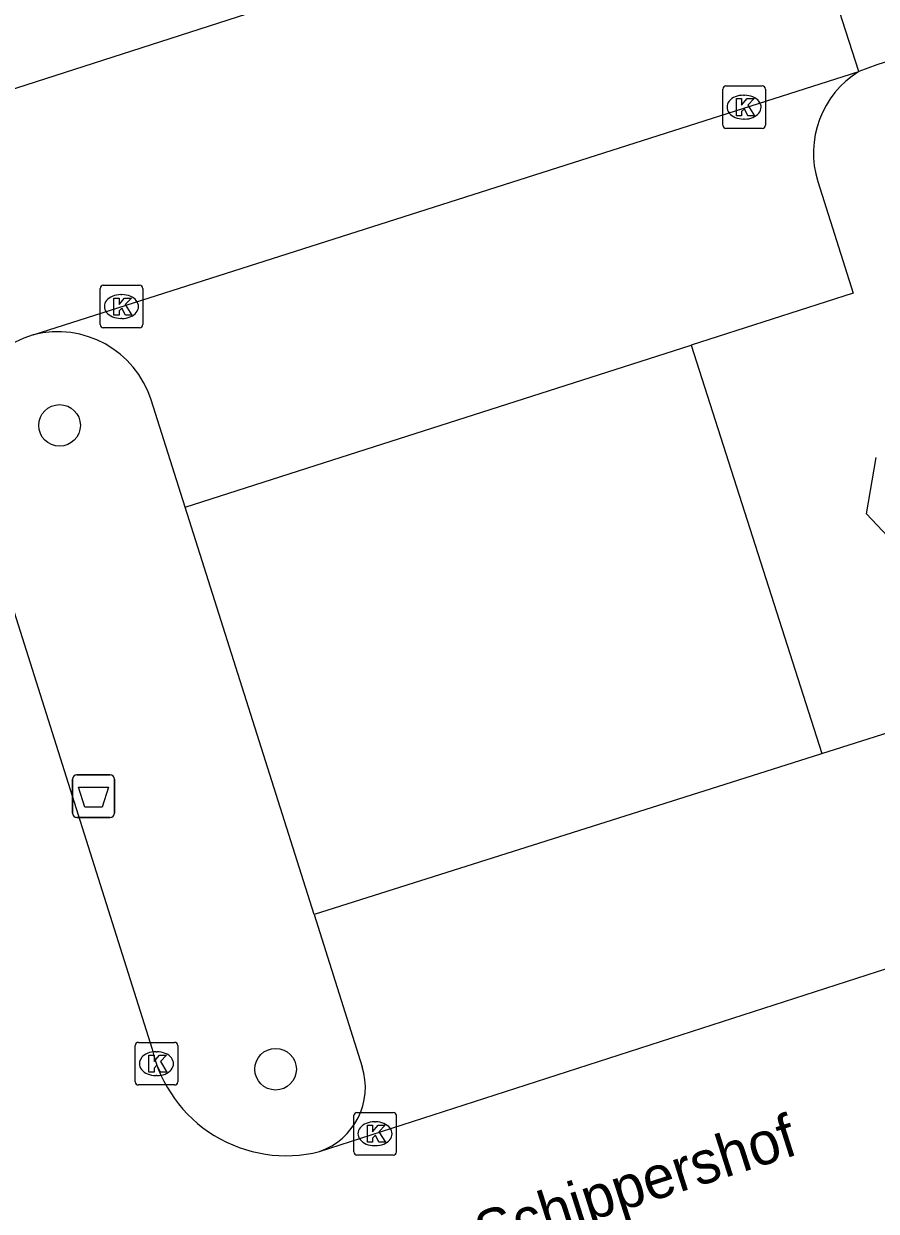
# Model space of a CAD drawing. Extents: x 159377 to 159983, y 382996 to 383595.
# Drawn here: x 159523.61 to 159543.65, y 383099.82 to 383127.71 of the extents above; entities that cross this region are included whole.
import ezdxf

# ---------------------------------------------------------------- set-up
doc = ezdxf.new("R2010")
doc.units = 0
for name, color, linetype in [('IMGEO_Afvalbak', 7, 'Continuous'), ('IMGEO_Boom', 7, 'Continuous'), ('IMGEO_Groenvoorziening', 7, 'Continuous'), ('IMGEO_Kolk', 7, 'Continuous'), ('IMGEO_Openbare_ruimte_label', 7, 'Continuous'), ('IMGEO_Parkeervlak_open', 7, 'Continuous'), ('IMGEO_Rijbaan_lokaal_open', 7, 'Continuous')]:
    doc.layers.add(name, color=color, linetype=linetype)

msp = doc.modelspace()

# ---------------------------------------------------------------- linework, layer by layer
at = {"layer": 'IMGEO_Afvalbak'}
for p, q in [((159524.758, 383109.167), (159524.758, 383109.967)), ((159524.758, 383109.967), (159524.758, 383109.167)), ((159524.858, 383110.067), (159525.648, 383110.067)), ((159525.648, 383110.067), (159524.858, 383110.067)), ((159525.748, 383109.967), (159525.748, 383109.167)), ((159525.748, 383109.167), (159525.748, 383109.967)), ((159525.648, 383109.067), (159524.858, 383109.067)), ((159524.858, 383109.067), (159525.648, 383109.067))]:
    msp.add_line(p, q, dxfattribs=at)
msp.add_lwpolyline([(159524.901, 383109.781), (159525.605, 383109.781), (159525.456, 383109.311), (159525.05, 383109.311), (159524.901, 383109.781)], dxfattribs=at)
for centre, start, end in [((159524.858, 383109.967), 90, 180), ((159524.858, 383109.967), 90, 180), ((159525.648, 383109.967), 0, 90), ((159525.648, 383109.967), 360, 90), ((159524.858, 383109.167), 180, 270), ((159524.858, 383109.167), 180, 270), ((159525.648, 383109.167), 270, 0), ((159525.648, 383109.167), 270, 0)]:
    msp.add_arc(centre, 0.1, start, end, dxfattribs=at)
at = {"layer": 'IMGEO_Boom'}
for centre in [(159524.456, 383118.278), (159529.533, 383103.152)]:
    msp.add_circle(centre, 0.489, dxfattribs=at)
at = {"layer": 'IMGEO_Groenvoorziening'}
for points in [[(159539.299, 383120.164), (159542.373, 383110.568)], [(159544.43, 383115.124), (159543.419, 383116.198), (159543.65, 383117.526)], [(159530.436, 383106.788), (159527.406, 383116.357)]]:
    msp.add_lwpolyline(points, dxfattribs=at)
at = {"layer": 'IMGEO_Kolk'}
for p, q in [((159540.042, 383125.329), (159540.042, 383126.181)), ((159540.117, 383126.255), (159540.969, 383126.255)), ((159541.043, 383126.181), (159541.043, 383125.329)), ((159540.53, 383126.035), (159540.555, 383126.035)), ((159540.553, 383125.475), (159540.528, 383125.475)), ((159540.969, 383125.255), (159540.117, 383125.255)), ((159525.409, 383120.645), (159525.409, 383121.497)), ((159525.484, 383121.571), (159526.336, 383121.571)), ((159526.41, 383121.497), (159526.41, 383120.645)), ((159525.897, 383121.351), (159525.922, 383121.351)), ((159526.336, 383120.571), (159525.484, 383120.571)), ((159525.92, 383120.791), (159525.895, 383120.791)), ((159526.307, 383103.783), (159527.159, 383103.783)), ((159526.232, 383102.857), (159526.232, 383103.709)), ((159526.72, 383103.563), (159526.745, 383103.563)), ((159527.233, 383103.709), (159527.233, 383102.857)), ((159526.743, 383103.003), (159526.718, 383103.003)), ((159527.159, 383102.783), (159526.307, 383102.783)), ((159531.444, 383102.136), (159532.296, 383102.136)), ((159531.369, 383101.21), (159531.369, 383102.062)), ((159531.857, 383101.916), (159531.882, 383101.916)), ((159532.37, 383102.062), (159532.37, 383101.21)), ((159531.88, 383101.356), (159531.855, 383101.356)), ((159532.296, 383101.136), (159531.444, 383101.136))]:
    msp.add_line(p, q, dxfattribs=at)
for points in [[(159540.042, 383125.329), (159540.042, 383126.181)], [(159540.117, 383126.255), (159540.969, 383126.255)], [(159541.043, 383126.181), (159541.043, 383125.329)], [(159540.363, 383125.955), (159540.486, 383125.955), (159540.486, 383125.804), (159540.616, 383125.955), (159540.78, 383125.955), (159540.634, 383125.804), (159540.787, 383125.555), (159540.635, 383125.555), (159540.55, 383125.719), (159540.486, 383125.652), (159540.486, 383125.555), (159540.363, 383125.555), (159540.363, 383125.955)], [(159540.969, 383125.255), (159540.117, 383125.255)], [(159525.409, 383120.645), (159525.409, 383121.497)], [(159525.484, 383121.571), (159526.336, 383121.571)], [(159526.41, 383121.497), (159526.41, 383120.645)], [(159525.73, 383121.271), (159525.853, 383121.271), (159525.853, 383121.12), (159525.983, 383121.271), (159526.147, 383121.271), (159526.001, 383121.12), (159526.154, 383120.871), (159526.002, 383120.871), (159525.917, 383121.035), (159525.853, 383120.968), (159525.853, 383120.871), (159525.73, 383120.871), (159525.73, 383121.271)], [(159526.336, 383120.571), (159525.484, 383120.571)], [(159526.307, 383103.783), (159527.159, 383103.783)], [(159526.232, 383102.857), (159526.232, 383103.709)], [(159527.233, 383103.709), (159527.233, 383102.857)], [(159526.553, 383103.483), (159526.676, 383103.483), (159526.676, 383103.332), (159526.806, 383103.483), (159526.97, 383103.483), (159526.824, 383103.332), (159526.977, 383103.083), (159526.825, 383103.083), (159526.74, 383103.247), (159526.676, 383103.18), (159526.676, 383103.083), (159526.553, 383103.083), (159526.553, 383103.483)], [(159527.159, 383102.783), (159526.307, 383102.783)], [(159531.444, 383102.136), (159532.296, 383102.136)], [(159531.369, 383101.21), (159531.369, 383102.062)], [(159531.69, 383101.836), (159531.813, 383101.836), (159531.813, 383101.685), (159531.943, 383101.836), (159532.107, 383101.836), (159531.961, 383101.685), (159532.114, 383101.436), (159531.962, 383101.436), (159531.877, 383101.6), (159531.813, 383101.533), (159531.813, 383101.436), (159531.69, 383101.436), (159531.69, 383101.836)], [(159532.37, 383102.062), (159532.37, 383101.21)], [(159532.296, 383101.136), (159531.444, 383101.136)]]:
    msp.add_lwpolyline(points, dxfattribs=at)
for centre, start, end in [((159540.119, 383126.179), 91.552, 178.448), ((159540.119, 383126.179), 91.552, 178.448), ((159540.967, 383126.179), 1.552, 88.448), ((159540.967, 383126.179), 1.552, 88.448), ((159540.119, 383125.331), 181.552, 268.448), ((159540.119, 383125.331), 181.552, 268.448), ((159540.967, 383125.331), 271.552, 358.448), ((159540.967, 383125.331), 271.552, 358.448), ((159525.486, 383121.495), 91.552, 178.448), ((159525.486, 383121.495), 91.552, 178.448), ((159526.334, 383121.495), 1.552, 88.448), ((159526.334, 383121.495), 1.552, 88.448), ((159525.486, 383120.647), 181.552, 268.448), ((159525.486, 383120.647), 181.552, 268.448), ((159526.334, 383120.647), 271.552, 358.448), ((159526.334, 383120.647), 271.552, 358.448), ((159526.309, 383103.707), 91.552, 178.448), ((159526.309, 383103.707), 91.552, 178.448), ((159527.157, 383103.707), 1.552, 88.448), ((159527.157, 383103.707), 1.552, 88.448), ((159526.309, 383102.859), 181.552, 268.448), ((159526.309, 383102.859), 181.552, 268.448), ((159527.157, 383102.859), 271.552, 358.448), ((159527.157, 383102.859), 271.552, 358.448), ((159531.446, 383102.06), 91.552, 178.448), ((159531.446, 383102.06), 91.552, 178.448), ((159532.294, 383102.06), 1.552, 88.448), ((159532.294, 383102.06), 1.552, 88.448), ((159531.446, 383101.212), 181.552, 268.448), ((159531.446, 383101.212), 181.552, 268.448), ((159532.294, 383101.212), 271.552, 358.448), ((159532.294, 383101.212), 271.552, 358.448)]:
    msp.add_arc(centre, 0.0765, start, end, dxfattribs=at)
for centre, major_axis, ratio, start_param, end_param in [((159540.529, 383125.755), (-0.387, 0.002), 0.722429, 4.712389, 7.853982), ((159540.554, 383125.755), (-0.39, 0.002), 0.717154, 1.570796, 4.712389), ((159525.896, 383121.071), (-0.387, 0.002), 0.722429, 4.712389, 7.853982), ((159525.921, 383121.071), (-0.39, 0.002), 0.717154, 1.570796, 4.712389), ((159526.719, 383103.283), (-0.387, 0.002), 0.722429, 4.712389, 7.853982), ((159526.744, 383103.283), (-0.39, 0.002), 0.717154, 1.570796, 4.712389), ((159531.856, 383101.636), (-0.387, 0.002), 0.722429, 4.712389, 7.853982), ((159531.881, 383101.636), (-0.39, 0.002), 0.717154, 1.570796, 4.712389)]:
    msp.add_ellipse(centre, major_axis=major_axis, ratio=ratio, start_param=start_param, end_param=end_param, dxfattribs=at)
at = {"layer": 'IMGEO_Parkeervlak_open'}
for points in [[(159542.278, 383124.005), (159543.109, 383121.384), (159539.299, 383120.164)], [(159527.406, 383116.357), (159530.265, 383117.272), (159539.299, 383120.164)], [(159527.406, 383116.357), (159526.609, 383118.875)], [(159542.373, 383110.568), (159546.154, 383111.766), (159546.242, 383111.488), (159547.042, 383108.961)], [(159542.373, 383110.568), (159542.341, 383110.558), (159539.767, 383109.743), (159539.766, 383109.743), (159530.436, 383106.788)], [(159530.436, 383106.788), (159531.568, 383103.212)]]:
    msp.add_lwpolyline(points, dxfattribs=at)
for centre, radius, start, end in [((159544.411, 383124.681), 2.238, 121.4381, 197.581), ((159524.414, 383118.172), 2.305, 17.7667, 104.5038), ((159530.041, 383102.73), 1.601, 289.179, 17.5071)]:
    msp.add_arc(centre, radius, start, end, dxfattribs=at)
at = {"layer": 'IMGEO_Rijbaan_lokaal_open'}
for points in [[(159516.455, 383123.963), (159541.49, 383132.018)], [(159543.244, 383126.59), (159541.49, 383132.018)], [(159544.352, 383126.971), (159543.66, 383126.749), (159543.244, 383126.59)], [(159523.837, 383120.403), (159543.244, 383126.59)], [(159522.203, 383117.611), (159526.631, 383103.627)], [(159530.567, 383101.218), (159549.018, 383107.169)]]:
    msp.add_lwpolyline(points, dxfattribs=at)
for centre, radius, start, end in [((159524.516, 383118.131), 2.371, 106.6512, 192.6727), ((159529.778, 383104.348), 3.228, 192.9085, 284.1547)]:
    msp.add_arc(centre, radius, start, end, dxfattribs=at)

# ---------------------------------------------------------------- texts
at = {"layer": 'IMGEO_Openbare_ruimte_label'}
msp.add_text('Schippershof', height=1, rotation=17.7643, dxfattribs=at).set_placement((159534.42, 383098.782))

doc.saveas('drawing.dxf')
